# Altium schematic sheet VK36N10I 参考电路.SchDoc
size A4
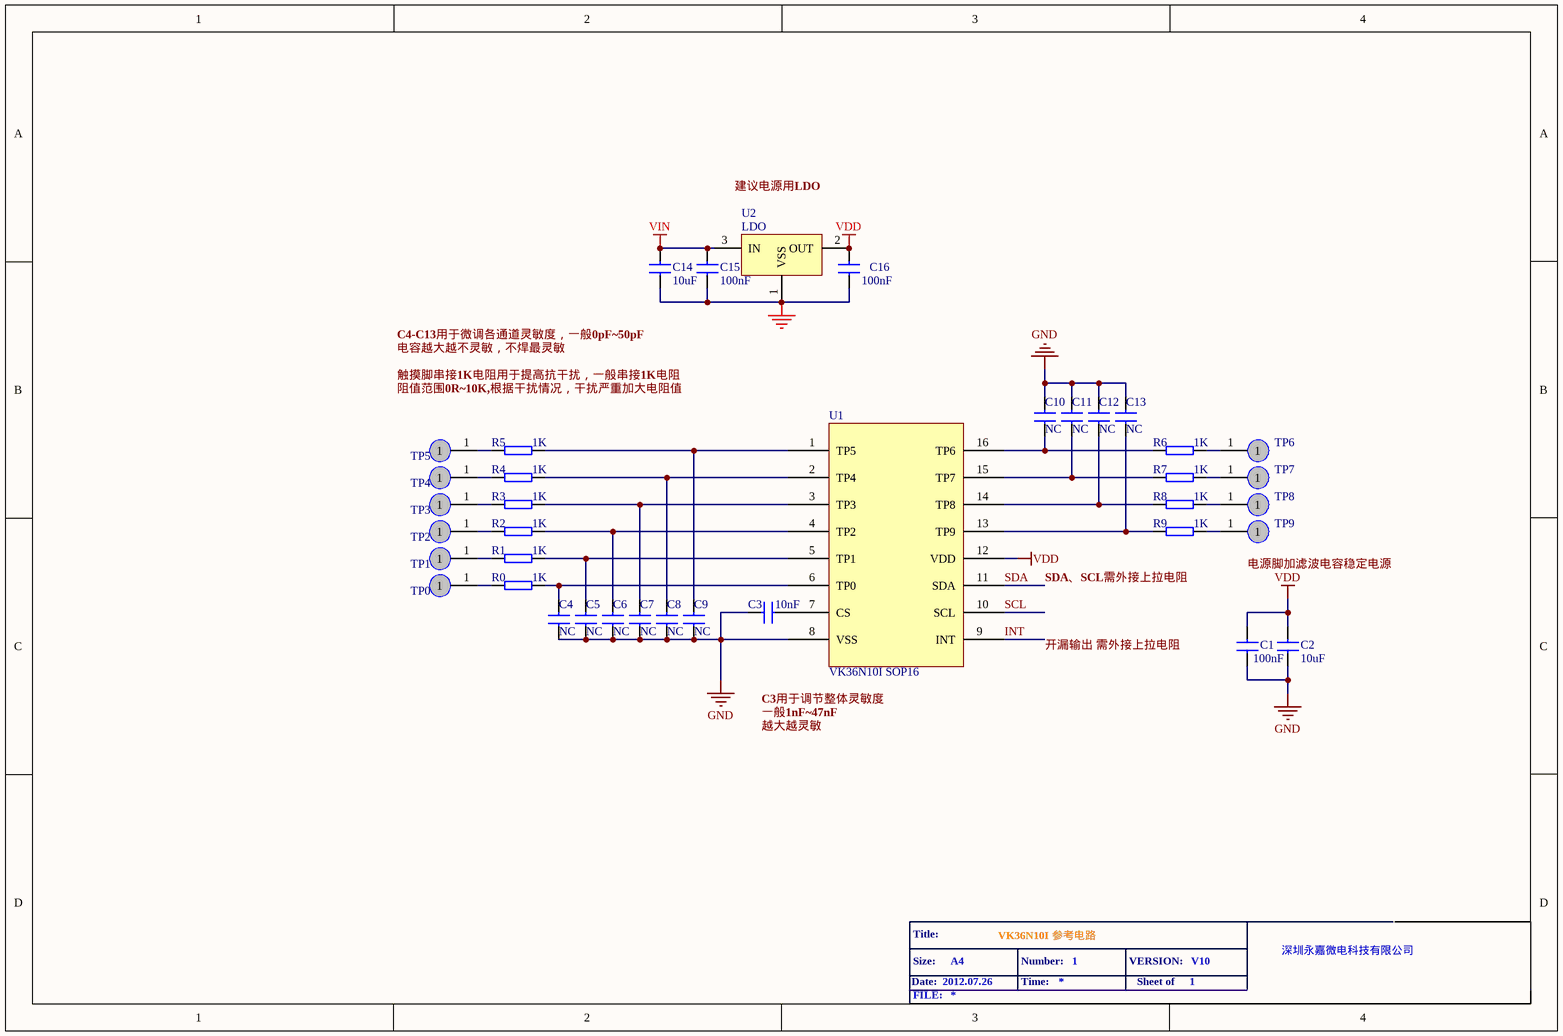
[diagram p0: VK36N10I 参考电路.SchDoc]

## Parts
C1  100nF  [0603-C]
C2  10uF  [0603-C]
C3  value 10nF  [0603-C]  (hidden comment: 10uF)
C4  value NC  [0603-C]  (hidden comment: 10uF)
C5  value NC  [0603-C]  (hidden comment: 10uF)
C6  value NC  [0603-C]  (hidden comment: 10uF)
C7  value NC  [0603-C]  (hidden comment: 10uF)
C8  value NC  [0603-C]  (hidden comment: 10uF)
C9  value NC  [0603-C]  (hidden comment: 10uF)
C10  value NC  [0603-C]  (hidden comment: 10uF)
C11  value NC  [0603-C]  (hidden comment: 10uF)
C12  value NC  [0603-C]  (hidden comment: 10uF)
C13  value NC  [0603-C]  (hidden comment: 10uF)
C14  10uF  [0805-C]
C15  100nF  [0805-C]
C16  100nF  [0805-C]
R0  1K  [0603-R]
R1  1K  [0603-R]
R2  1K  [0603-R]
R3  1K  [0603-R]
R4  1K  [0603-R]
R5  1K  [0603-R]
R6  1K  [0603-R]
R7  1K  [0603-R]
R8  1K  [0603-R]
R9  1K  [0603-R]
TP0  TPAD  [TP-PAD0]  (value not drawn)
TP1  TPAD  [TP-PAD0]  (value not drawn)
TP2  TPAD  [TP-PAD0]  (value not drawn)
TP3  TPAD  [TP-PAD0]  (value not drawn)
TP4  TPAD  [TP-PAD0]  (value not drawn)
TP5  TPAD  [TP-PAD0]  (value not drawn)
TP6  TPAD  [TP-PAD0]  (value not drawn)
TP7  TPAD  [TP-PAD0]  (value not drawn)
TP8  TPAD  [TP-PAD0]  (value not drawn)
TP9  TPAD  [TP-PAD0]  (value not drawn)
U1  VK36N10I SOP16
U2  LDO  [SOT-23]

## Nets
GND: C1.2 C2.2 C3.2 C4.1 C5.1 C6.1 C7.1 C8.1 C9.1 C10.2 C11.2 C12.2 C13.2 C14.2 C15.2 C16.2 U1.8(VSS) U2.1(VSS)
VDD: C1.1 C2.1 C16.1 U1.12(VDD) U2.2(OUT)
VIN: C14.1 C15.1 U2.3(IN)
INT: U1.9(INT)
SCL: U1.10(SCL)
SDA: U1.11(SDA)
NetC3_1: C3.1 U1.7(CS)
NetC4_2: C4.2 R0.2 U1.6(TP0)
NetC5_2: C5.2 R1.1 U1.5(TP1)
NetC6_2: C6.2 R2.1 U1.4(TP2)
NetC7_2: C7.2 R3.1 U1.3(TP3)
NetC8_2: C8.2 R4.1 U1.2(TP4)
NetC9_2: C9.2 R5.1 U1.1(TP5)
NetC10_1: C10.1 R6.1 U1.16(TP6)
NetC11_1: C11.1 R7.1 U1.15(TP7)
NetC12_1: C12.1 R8.1 U1.14(TP8)
NetC13_1: C13.1 R9.1 U1.13(TP9)
NetR0_1: R0.1 TP0.1
NetR1_2: R1.2 TP1.1
NetR2_2: R2.2 TP2.1
NetR3_2: R3.2 TP3.1
NetR4_2: R4.2 TP4.1
NetR5_2: R5.2 TP5.1
NetR6_2: R6.2 TP6.1
NetR7_2: R7.2 TP7.1
NetR8_2: R8.2 TP8.1
NetR9_2: R9.2 TP9.1

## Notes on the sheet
- 建议电源用LDO
- 触摸脚串接1K电阻用于提高抗干扰，一般串接1K电阻
- C4-C13用于微调各通道灵敏度，一般0pF~50pF
- 电容越大越不灵敏，不焊最灵敏
- 阻值范围0R
  0K,根据干扰情况，干扰严重加大电阻值
- SDA、SCL需外接上拉电阻
- (near TP9) 电源脚加滤波电容稳定电源
- 开漏输出 需外接上拉电阻
- C3用于调节整体灵敏度
- 一般1nF~47nF
- 越大越灵敏
- Date:
- Title:
- Size:
- 2012.07.26
- A4
- VK36N10I 参考电路
- Number:
- Time:
- 1
- VERSION:
- Sheet of
- V10
- 深圳永嘉微电科技有限公司
- FILE:

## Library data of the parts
C1-C16 = CAP: Capacitor
R0-R9 = RES: Resistor
TP0-TP9 = TPAD: TESTING
U2 = V6206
